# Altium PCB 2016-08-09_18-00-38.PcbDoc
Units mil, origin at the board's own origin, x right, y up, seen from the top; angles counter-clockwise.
Board outline 2000 x 4000 mil, 4 copper layers (Top Layer, MidLayer1, MidLayer2, Bottom Layer); 19 components, 14 nets, 66 pads, 68 vias.
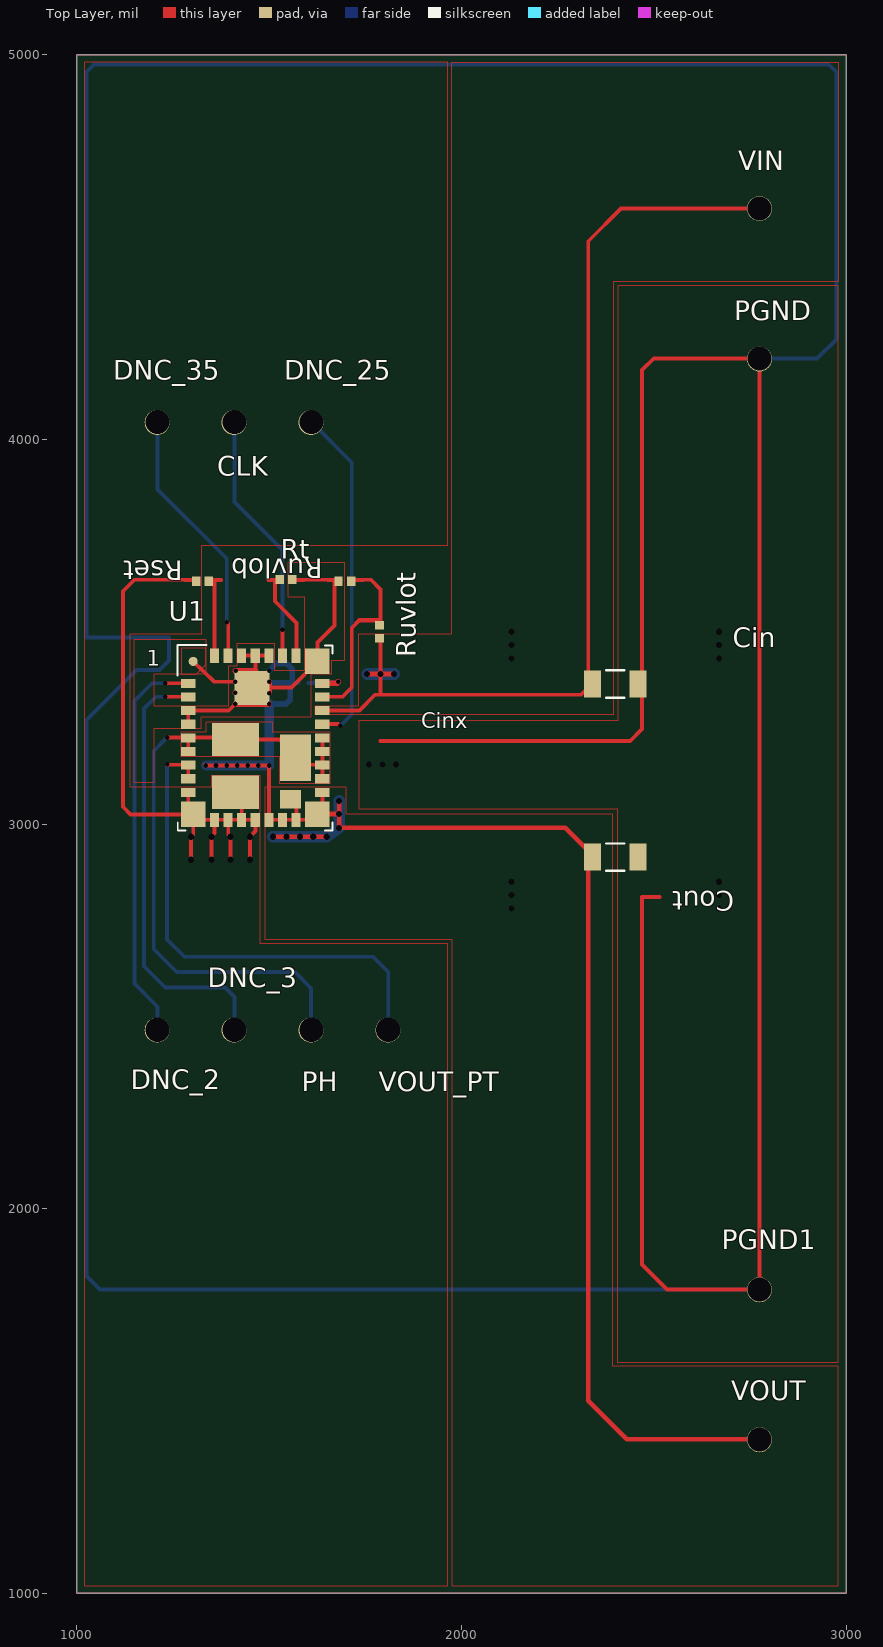
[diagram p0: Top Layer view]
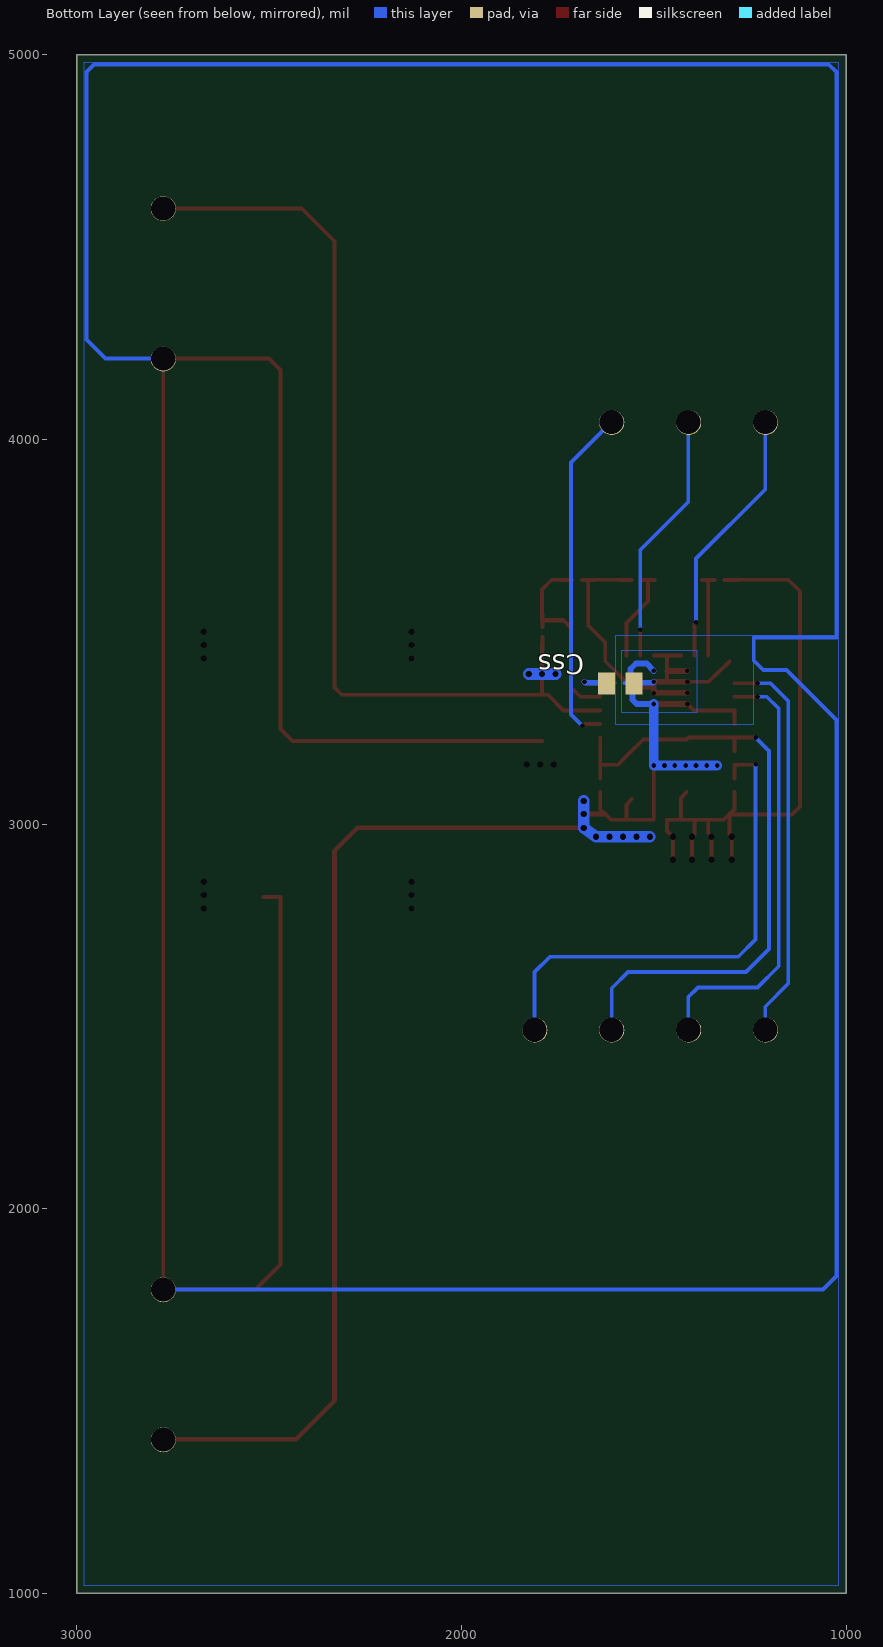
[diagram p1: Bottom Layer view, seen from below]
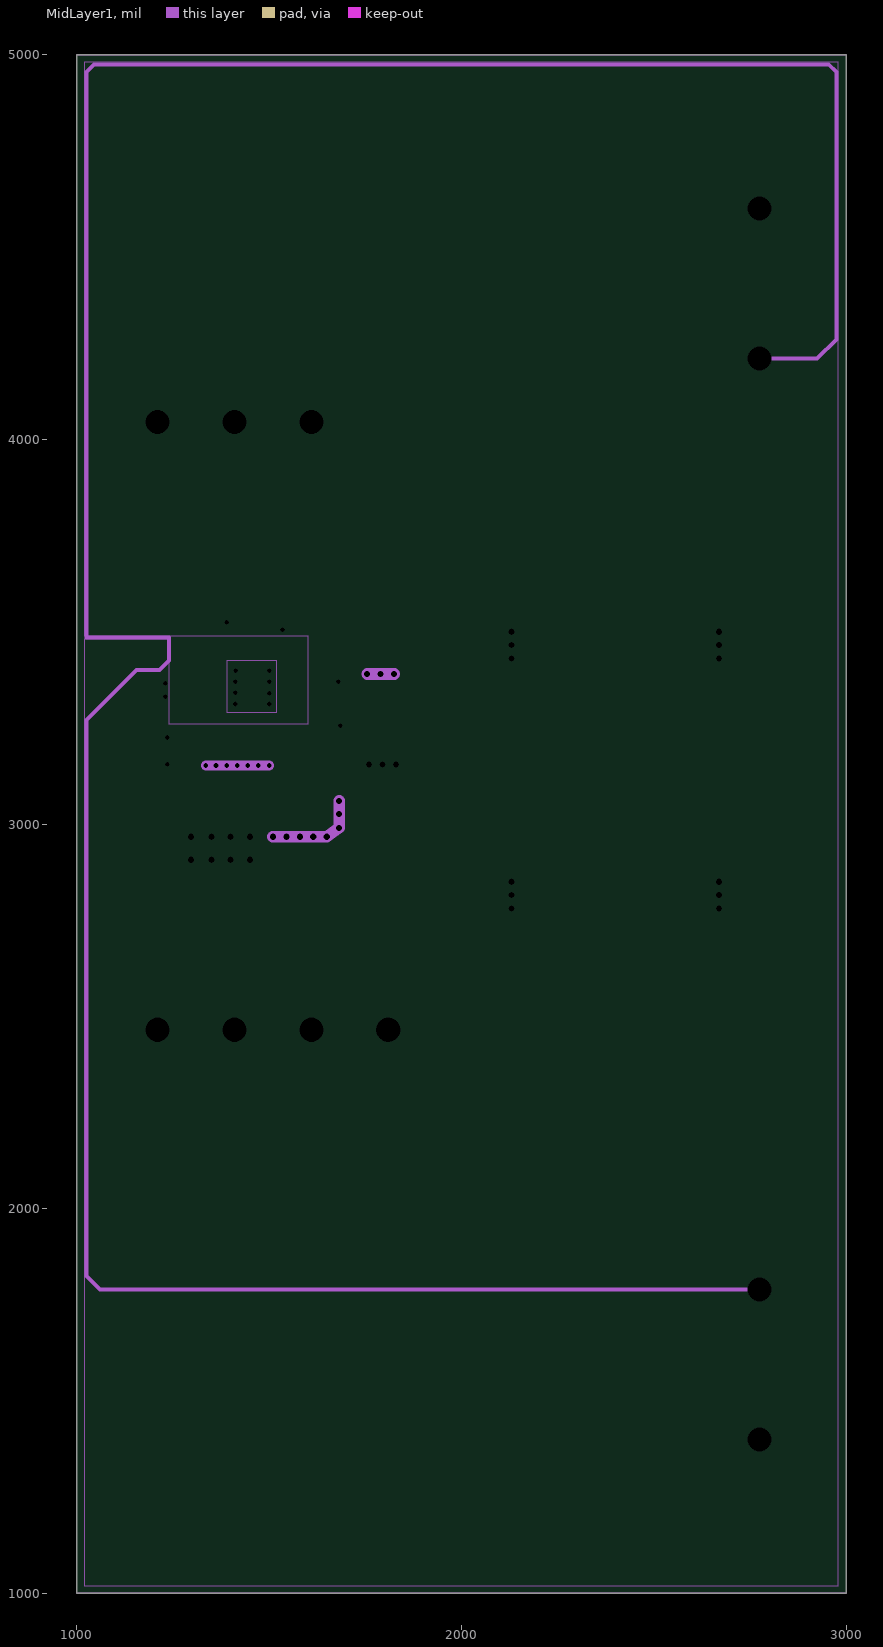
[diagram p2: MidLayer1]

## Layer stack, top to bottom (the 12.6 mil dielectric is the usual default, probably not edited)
Top Layer: signal copper 1.4
Dielectric: core 12.6, FR-4, Dk 4.8
MidLayer1: signal copper 1.4
Dielectric: prepreg 12.6, FR-4, Dk 4.8
MidLayer2: signal copper 1.4
Dielectric: core 12.6, FR-4, Dk 4.8
Bottom Layer: signal copper 1.4

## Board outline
1000,1000 3000,1000 3000,5000 1000,5000

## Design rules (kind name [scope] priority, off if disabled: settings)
PlaneConnect [All] p0: scope1count=1 scope1_0_kind=Board scope1_0_value=Board scope2count=1 scope2_0_kind=Board scope2_0_value=Board commentlength=0 planeconnectstyle=Direct reliefexpansion=20 reliefentries=4 reliefconductorwidth=10 reliefairgap=10
PlaneConnect [All] p1: planeconnectstyle=Direct reliefexpansion=20 reliefentries=4 reliefconductorwidth=10 reliefairgap=10
PolygonConnect [All] p0: scope1count=1 scope1_0_kind=Board scope1_0_value=Board scope2count=1 scope2_0_kind=Board scope2_0_value=Board commentlength=0 connectstyle=Direct reliefconductorwidth=10 reliefentries=4 polygonreliefangle="90 Angle"
PolygonConnect [All] p1: connectstyle=Direct reliefconductorwidth=10 reliefentries=4 polygonreliefangle="90 Angle"

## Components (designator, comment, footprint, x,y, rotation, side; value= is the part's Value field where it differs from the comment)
Cin "" 1206 2400,3364 r0 top
CLK "" TP-1502 1409,4044 r0 top
Cout "" 1206_190 2400,2914 r180 top
Css "" 0805 1587,3365 r180 bottom
DNC_2 "" TP-1502 1209,2464 r0 top
DNC_3 "" TP-1502 1409,2464 r0 top
DNC_25 "" TP-1502 1609,4044 r0 top
DNC_35 "" TP-1502 1209,4044 r0 top
PGND "" TP-1502 2775,4209 r0 top
PGND1 "" TP-1502 2775,1789 r0 top
PH "" TP-1502 1609,2464 r0 top
Rset "" 0402 1327,3631 r180 top
Rt "" 0402 1544,3636 r0 top
Ruvlob "" 0402 1697,3631 r180 top
Ruvlot "" 0402 1787,3500 r90 top
U1 "" RKG0041A 1464,3224 r0 top
VIN "" TP-1502 2775,4600 r0 top
VOUT "" TP-1502 2775,1399 r0 top
VOUT_PT "" TP-1502 1809,2464 r0 top

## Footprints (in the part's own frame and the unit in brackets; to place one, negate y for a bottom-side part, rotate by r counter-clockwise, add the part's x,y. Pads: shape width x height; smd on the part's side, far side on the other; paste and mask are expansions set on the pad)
0402 [mil]
  rect 22x24 smd: 1(-16.5,0) 2(16.5,0)
0805 [mil]
  rect 44x57 smd: 1(35.5,0) 2(-35.5,0)
1206 [mil]
  rect 44x71 smd: 1(-59,0) 2(59,0)
  silkscreen extent -24,-36 24,36
1206_190 [mil]
  rect 44x71 smd: 1(-59,0) 2(59,0)
  silkscreen extent -24,-36 24,36
RKG0041A [mm]
  round 0.6 smd: 1(-4.1,5.05)
  rect 0.95x0.6 smd: 2(-4.42,3.6) 3(-4.42,2.7) 4(-4.42,1.8) 5(-4.42,0.9) 6(-4.42,0) 7(-4.42,-0.9) 8(-4.42,-1.8) 9(-4.42,-2.7) 10(-4.42,-3.6) 20(4.42,-3.6) 21(4.42,-2.7) 22(4.42,-1.8) 23(4.42,-0.9) 24(4.42,0) 25(4.42,0.9) 26(4.42,1.8) 27(4.42,2.7) 28(4.42,3.6)
  rect 1.6x1.7 smd: 11(-4.1,-5.05) 19(4.1,-5.05) 29(4.1,5.05)
  rect 0.6x0.95 smd: 12(-2.7,-5.425) 13(-1.8,-5.425) 14(-0.9,-5.425) 15(0,-5.425) 16(0.9,-5.425) 17(1.8,-5.425) 18(2.7,-5.425) 30(2.7,5.425) 31(1.8,5.425) 32(0.9,5.425) 33(0,5.425) 34(-0.9,5.425) 35(-1.8,5.425) 36(-2.7,5.425)
  rect 2.3x2.25 smd: 37(-0.22,3.3)
  rect 3.1x2.2 smd: 38(-1.3,-0.11) 39(-1.3,-3.59)
  rect 1.4x1.24 smd: 40(2.33,-4.06)
  rect 2.04x3.05 smd: 41(2.65,-1.32)
  silkscreen extent -5.13,-6.11 5.12,6.12
TP-1502 [mil]
  round 65 / inner round 0 / far side round 65 hole 32: 1(0,0)

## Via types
v1: diameter 0, hole 16, Top Layer to Bottom Layer, 34 vias
v2: diameter 0, hole 12, Top Layer to Bottom Layer, 23 vias
v3: diameter 0, hole 63, Top Layer to Bottom Layer, 11 vias

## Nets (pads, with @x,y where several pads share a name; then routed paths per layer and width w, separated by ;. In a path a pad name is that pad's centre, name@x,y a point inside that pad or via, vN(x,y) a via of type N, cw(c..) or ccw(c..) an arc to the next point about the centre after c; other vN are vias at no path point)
0: Cin.2 Cout.1 PGND1.1 PGND.1 Rset.2 U1.10 U1.11 U1.12 U1.13 U1.14 U1.15 U1.39 | length 23658.6
  Top Layer w10: 1283,3634.5 Rset.2@1316,3634.5 ; U1.10@1290,3083 1290,3038 U1.11@1303,3026 ; v1(1297,2907) v1(1297,2967) 1303,2973 U1.11@1303,3026 ; Rset.2@1300,3635 1150,3635 1120,3605 1120,3045 1140,3025 1302,3025 U1.11@1303,3026 ; v1(1350,2907) v1(1350,2967) 1358,2976 U1.12@1358,3011 ; v1(1400,2907) v1(1400,2967) 1394,2973 U1.13@1394,3011 ; U1.39@1414,3083 1429,3068 U1.14@1429,3011 ; v1(1450,2907) v1(1450,2967) 1465,2982 1465,3011 U1.14@1429,3011 ; 1790,3216 2439,3216 2470,3247 2470,3460 2470,4180 2500,4210 v3(2775,4210) v3(2775,1790) 2535,1790 2470,1855 2470,2810 2515,2810 ; U1.11@1303,3026 1318,3011 U1.12@1358,3011 ; U1.12@1358,3011 U1.13@1394,3011 ; U1.13@1394,3011 U1.14@1429,3011
  MidLayer1 w10: v3(2775,1790) 1060,1790 1025,1825 1025,3270 1155,3400 1215,3400 1240,3425 1240,3485 1025,3485 1025,4955 1045,4975 2955,4975 2975,4955 2975,4260 2925,4210 v3(2775,4210)
  Bottom Layer w10: v3(2775,1790) 1060,1790 1025,1825 1025,3270 1155,3400 1215,3400 1240,3425 1240,3485 1025,3485 1025,4955 1045,4975 2955,4975 2975,4955 2975,4260 2925,4210 v3(2775,4210)
  other v1: 2670,2780 2670,2815 2670,2850 1760,3155 1795,3155 1830,3155 2670,3430 2670,3465 2670,3500
1: Cout.2 Css.1 Rt.2 Ruvlob.2 U1.1 U1.4 U1.5 U1.16 U1.17 U1.18 U1.19 U1.20 U1.29 U1.32 U1.33 U1.34 U1.37 U1.40 VOUT.1 | length 6093.6
  Top Layer w10: U1.5@1290,3260 1290,3295 1395,3295 v2(1412,3312) ; U1.1@1303,3423 1357,3370 v2(1412,3370) ; 1333,3154 v2(1335,3152) v2(1362,3152) v2(1390,3152) v2(1417,3152) v2(1445,3152) v2(1472,3152) v2(1500,3152) 1500,3151 1500,3011 1535,3011 U1.18@1571,3011 ; U1.34@1429,3438 U1.33@1465,3438 ; U1.37@1465,3370 1465,3398 U1.33@1465,3438 ; U1.37@1500,3355 1558,3355 1626,3423 1626,3472 1670,3516 1670,3635 1574,3635 ; U1.32@1500,3438 U1.33@1465,3438 ; U1.40@1557,3065 1571,3050 U1.18@1571,3011 ; Rt.2@1557,3634.5 1590,3634.5 ; U1.20@1639,3083 1639,3038 1626,3026 1611,3011 U1.18@1571,3011 ; 1653,3634.5 Ruvlob.2@1686,3634.5
  Top Layer w12: v1(1510,2967) v1(1545,2967) v1(1580,2967) v1(1615,2967) v1(1650,2967) ; U1.19@1626,3026 v1(1682,3026) ; v1(1682,3060) v1(1682,3026) ; v3(2775,1400) 2430,1400 2330,1500 2330,2810 2330,2930 2270,2990 v1(1682,2990) v1(1682,3026)
  Top Layer w15: v2(1412,3312) v2(1500,3312) ; v2(1412,3341) 1500,3341 1500,3355 v2(1500,3370) 1465,3370 v2(1412,3370) ; v2(1413,3398) U1.37@1465,3398
  MidLayer1 w25: v2(1335,3152) v2(1362,3152) v2(1390,3152) v2(1417,3152) v2(1445,3152) v2(1472,3152) v2(1500,3152)
  MidLayer1 w30: v1(1510,2967) v1(1545,2967) v1(1580,2967) v1(1615,2967) v1(1650,2967) v1(1682,2990) v1(1682,3026) v1(1682,3060)
  Bottom Layer w10: Css.1@1543,3366.5 1576,3366.5
  Bottom Layer w15: v2(1500,3312) 1544,3312 1555,3323 1555,3367 1502,3367 ; v2(1500,3370) 1502,3367 ; v2(1500,3398) 1518,3417 1546,3417 1560,3403 1560,3367 1502,3367
  Bottom Layer w25: v2(1335,3152) v2(1362,3152) v2(1390,3152) v2(1417,3152) v2(1445,3152) v2(1472,3152) v2(1500,3152) v2(1500,3312)
  Bottom Layer w30: v1(1510,2967) v1(1545,2967) v1(1580,2967) v1(1615,2967) v1(1650,2967) v1(1682,2990) v1(1682,3026) v1(1682,3060)
  other v1: 2130,2780 2130,2815 2130,2850
  other v2: 1500,3340
2: Ruvlob.1 Ruvlot.2 U1.27 | length 599
  Top Layer w10: U1.27@1639,3331 1691,3331 1715,3355 1715,3510 1734,3529 ; Ruvlob.1@1712,3634.5 1745,3634.5 ; 1729,3635 1765,3635 1790,3610 1790,3529 ; Ruvlot.2@1789.5,3512 1789.5,3545 ; 1734,3529 1735,3530 1789,3530 1790,3529 ; 1734,3529 1790,3529
3: Cin.1 Ruvlot.1 U1.26 VIN.1 | length 2733.4
  Top Layer w10: U1.26@1639,3295 1735,3295 1775,3336 1790,3336 ; 1789.5,3453 Ruvlot.1@1789.5,3486 ; 1790,3470 v1(1790,3390) 1790,3336 ; v3(2775,4600) 2415,4600 2330,4515 2330,3460 2330,3355 2311,3336 1790,3336
  Top Layer w12: v1(1755,3390) v1(1790,3390) v1(1825,3390)
  MidLayer1 w30: v1(1755,3390) v1(1790,3390) v1(1825,3390)
  Bottom Layer w30: v1(1755,3390) v1(1790,3390) v1(1825,3390)
  other v1: 2130,3430 2130,3465 2130,3500
4: Rt.1 U1.30 | length 253.2
  Top Layer w10: 1498,3634.5 Rt.1@1531,3634.5 ; 1515,3635 1515,3579 1571,3523 U1.30@1571,3438
5: Rset.1 U1.36 | length 230.4
  Top Layer w10: Rset.1@1342,3634.5 1375,3634.5 ; U1.36@1358,3438 1358,3634 1359,3635
8: PH.1 U1.6 U1.7 U1.21 U1.22 U1.23 U1.24 U1.38 U1.41 | length 1700.9
  Top Layer w10: v2(1235,3225) U1.6@1290,3225 ; U1.7@1290,3189 U1.6@1290,3225 ; U1.21@1639,3118 U1.22@1639,3154 ; U1.24@1639,3225 1639,3189 U1.22@1639,3154 ; U1.6@1290,3225 1410,3225 1414,3220 1527,3220 1569,3178 1593,3154 U1.22@1639,3154
  Bottom Layer w10: v2(1235,3225) 1200,3190 1200,2675 1260,2615 1567,2615 1609,2573 1609,2466 v3(1610,2465)
9: U1.8 U1.9 VOUT_PT.1 | length 1307.2
  Top Layer w10: v2(1235,3155) 1235,3154 1290,3154 U1.9@1290,3118
  Bottom Layer w10: v2(1235,3155) 1235,2700 1280,2655 1770,2655 1810,2615 v3(1810,2465)
10: DNC_35.1 U1.35 | length 683
  Top Layer w10: v2(1390,3525) 1394,3520 U1.35@1394,3438
  Bottom Layer w10: v3(1210,4045) 1210,3870 1390,3690 v2(1390,3525)
11: DNC_25.1 U1.25 | length 893.7
  Top Layer w10: U1.25@1639,3260 1679,3260 v2(1685,3255)
  Bottom Layer w10: v3(1610,4045) 1715,3940 1715,3285 v2(1685,3255)
12: DNC_3.1 U1.3 | length 1151
  Top Layer w10: v2(1230,3331) U1.3@1290,3331
  Bottom Layer w10: v2(1230,3331) 1206,3331 1175,3300 1175,2630 1230,2575 1385,2575 1410,2550 v3(1410,2465)
13: DNC_2.1 U1.2 | length 1038.9
  Top Layer w10: v2(1230,3366) U1.2@1290,3366
  Bottom Layer w10: v3(1210,2465) 1210,2525 1150,2585 1150,3320 1196,3366 v2(1230,3366)
14: CLK.1 U1.31 | length 658.8
  Top Layer w10: U1.31@1535,3438 1535,3504 v2(1535,3505)
  Bottom Layer w10: v3(1410,4045) 1410,3837 1535,3712 v2(1535,3505)
20: Css.2 U1.28 | length 137.9
  Top Layer w15: U1.28@1639,3366 1676,3366 v2(1680,3370)
  Bottom Layer w10: Css.2@1602,3366.5 Css.2@1635,3366.5
  Bottom Layer w15: Css.2@1619,3367 1677,3367 v2(1680,3370)

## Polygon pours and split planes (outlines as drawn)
1 on Top Layer " " (solid, pour order 0): 1272,3457 1272,3390 1310,3390 1335,3414 1335,3457
8 on Top Layer " " (solid, pour order 5): 1659,3238 1510,3238 1510,3265 1335,3265 1335,3238 1270,3238 1270,3176 1527,3176 1527,3106 1659,3106
1 on Top Layer " " (solid, pour order 6): 2980,1020 2980,1590 2394,1590 2394,3025 1700,3025 1700,3095 1489,3095 1489,2700 1975,2700 1975,1020
3 on Top Layer " " (solid, pour order 7): 2980,4980 2980,4410 2395,4410 2395,3284 1620,3284 1620,3308 1733,3308 1733,3495 1975,3495 1975,4980
1 on Top Layer " " (solid, pour order 8): 1200,3107 1150,3107 1150,3480 1335,3480 1335,3390 1200,3390 1200,3308 1395,3308 1395,3412 1417,3412 1417,3470 1514,3470 1514,3400 1593,3400 1593,3590 1550,3590 1550,3680 1695,3680 1695,3425 1661,3425 1661,3390 1608,3390 1608,3277 1322,3277 1322,3248 1200,3248
0 on Top Layer " " (solid, pour order 11): 1477,3125 1350,3125 1350,3095 1139,3095 1139,3495 1325,3495 1325,3725 1965,3725 1965,4980 1020,4980 1020,1020 1965,1020 1965,2689 1477,2689
0 on Top Layer " " (solid, pour order 12): 2980,4400 2406,4400 2406,3269 1733,3269 1733,3040 2405,3040 2405,1600 2980,1600
1 on Bottom Layer " " (solid, pour order 9): 1585,3450 1585,3290 1387,3290 1387,3450
0 on Bottom Layer " " (solid, pour order 13): 2980,4980 1020,4980 1020,3490 1600,3490 1600,3260 1240,3260 1240,3485 1020,3485 1020,1020 2980,1020
3 on MidLayer2 " " (solid, pour order 1): 2980,4980 1975,4980 1975,3495 1733,3495 1733,3284 2395,3284 2395,4410 2980,4410
1 on MidLayer2 " " (solid, pour order 2): 1275,3440 1275,3290 1655,3290 1655,3440
1 on MidLayer2 " " (solid, pour order 3): 1020,4980 1020,1020 2980,1020 2980,4400 2410,4400 2410,3270 1250,3270 1250,3505 1965,3505 1965,4980
1 on MidLayer1 " " (solid, pour order 4): 1390,3425 1390,3290 1520,3290 1520,3425
0 on MidLayer1 " " (solid, pour order 10): 2980,4980 1020,4980 1020,3490 1600,3490 1600,3260 1240,3260 1240,3480 1020,3480 1020,1020 2980,1020
no net on Top Paste "Top Layer-No Net" (solid, remove dead copper): 1510.26,3455.1 1488.61,3455.1 1488.61,3420.06 1510.26,3420.06
no net on Top Paste "Top Layer-No Net" (solid, remove dead copper): 1545.69,3455.1 1524.04,3455.1 1524.04,3420.06 1545.69,3420.06
no net on Top Paste "Top Layer-No Net" (solid, remove dead copper): 1581.13,3455.1 1559.47,3455.1 1559.47,3420.06 1581.13,3420.06
no net on Top Paste "Top Layer-No Net" (solid, remove dead copper): 1655.54,3354.91 1655.54,3376.56 1620.5,3376.56 1620.5,3354.91
no net on Top Paste "Top Layer-No Net" (solid, remove dead copper): 1655.54,3319.47 1655.54,3341.13 1620.5,3341.13 1620.5,3319.47
no net on Top Paste "Top Layer-No Net" (solid, remove dead copper): 1655.54,3284.04 1655.54,3305.69 1620.5,3305.69 1620.5,3284.04
no net on Top Paste "Top Layer-No Net" (solid, remove dead copper): 1655.54,3248.61 1655.54,3270.26 1620.5,3270.26 1620.5,3248.61
no net on Top Paste "Top Layer-No Net" (solid, remove dead copper): 1655.54,3213.17 1655.54,3234.83 1620.5,3234.83 1620.5,3213.17
no net on Top Paste "Top Layer-No Net" (solid, remove dead copper): 1655.54,3177.74 1655.54,3199.39 1620.5,3199.39 1620.5,3177.74
no net on Top Paste "Top Layer-No Net" (solid, remove dead copper): 1655.54,3142.31 1655.54,3163.96 1620.5,3163.96 1620.5,3142.31
no net on Top Paste "Top Layer-No Net" (solid, remove dead copper): 1655.54,3106.87 1655.54,3128.53 1620.5,3128.53 1620.5,3106.87
no net on Top Paste "Top Layer-No Net" (solid, remove dead copper): 1655.54,3071.44 1655.54,3093.09 1620.5,3093.09 1620.5,3071.44
no net on Top Paste "Top Layer-No Net" (solid, remove dead copper): 1549.83,3043.69 1549.83,3084.63 1530.14,3084.63 1530.14,3043.69
no net on Top Paste "Top Layer-No Net" (solid, remove dead copper): 1438.61,3348.02 1438.61,3314.55 1472.07,3314.55 1472.07,3348.02
no net on Top Paste "Top Layer-No Net" (solid, remove dead copper): 1356.52,3213.76 1356.52,3182.27 1406.91,3182.27 1406.91,3213.76
no net on Top Paste "Top Layer-No Net" (solid, remove dead copper): 1581.32,3043.69 1581.32,3084.63 1561.64,3084.63 1561.64,3043.69
no net on Top Paste "Top Layer-No Net" (solid, remove dead copper): 1649.83,3393.84 1649.83,3451.8 1601.01,3451.8 1601.01,3393.84
no net on Top Paste "Top Layer-No Net" (solid, remove dead copper): 1649.83,2996.2 1649.83,3054.16 1601.01,3054.16 1601.01,2996.2
no net on Top Paste "Top Layer-No Net" (solid, remove dead copper): 1326.99,2996.2 1326.99,3054.16 1278.17,3054.16 1278.17,2996.2
no net on Top Paste "Top Layer-No Net" (solid, remove dead copper): 1438.61,3393.29 1438.61,3359.83 1472.07,3359.83 1472.07,3393.29
no net on Top Paste "Top Layer-No Net" (solid, remove dead copper): 1356.52,3257.07 1356.52,3225.57 1406.91,3225.57 1406.91,3257.07
no net on Top Paste "Top Layer-No Net" (solid, remove dead copper): 1418.72,3257.07 1418.72,3225.57 1469.12,3225.57 1469.12,3257.07
no net on Top Paste "Top Layer-No Net" (solid, remove dead copper): 1418.72,3213.76 1418.72,3182.27 1469.12,3182.27 1469.12,3213.76
no net on Top Paste "Top Layer-No Net" (solid, remove dead copper): 1418.72,3076.76 1418.72,3045.26 1469.12,3045.26 1469.12,3076.76
no net on Top Paste "Top Layer-No Net" (solid, remove dead copper): 1418.72,3120.06 1418.72,3088.57 1469.12,3088.57 1469.12,3120.06
no net on Top Paste "Top Layer-No Net" (solid, remove dead copper): 1356.52,3120.06 1356.52,3088.57 1406.91,3088.57 1406.91,3120.06
no net on Top Paste "Top Layer-No Net" (solid, remove dead copper): 1356.52,3076.76 1356.52,3045.26 1406.91,3045.26 1406.91,3076.76
no net on Top Paste "Top Layer-No Net" (solid, remove dead copper): 1533.69,3177.94 1562.43,3177.94 1562.43,3228.33 1533.69,3228.33
no net on Top Paste "Top Layer-No Net" (solid, remove dead copper): 1574.24,3177.94 1602.98,3177.94 1602.98,3228.33 1574.24,3228.33
no net on Top Paste "Top Layer-No Net" (solid, remove dead copper): 1533.69,3115.73 1562.43,3115.73 1562.43,3166.13 1533.69,3166.13
no net on Top Paste "Top Layer-No Net" (solid, remove dead copper): 1574.24,3115.73 1602.98,3115.73 1602.98,3166.13 1574.24,3166.13
no net on Top Paste "Top Layer-No Net" (solid, remove dead copper): 1346.87,2992.9 1368.53,2992.9 1368.53,3027.94 1346.87,3027.94
no net on Top Paste "Top Layer-No Net" (solid, remove dead copper): 1382.31,2992.9 1403.96,2992.9 1403.96,3027.94 1382.31,3027.94
no net on Top Paste "Top Layer-No Net" (solid, remove dead copper): 1417.74,2992.9 1439.39,2992.9 1439.39,3027.94 1417.74,3027.94
no net on Top Paste "Top Layer-No Net" (solid, remove dead copper): 1453.17,2992.9 1474.83,2992.9 1474.83,3027.94 1453.17,3027.94
no net on Top Paste "Top Layer-No Net" (solid, remove dead copper): 1488.61,2992.9 1510.26,2992.9 1510.26,3027.94 1488.61,3027.94
no net on Top Paste "Top Layer-No Net" (solid, remove dead copper): 1524.04,2992.9 1545.69,2992.9 1545.69,3027.94 1524.04,3027.94
no net on Top Paste "Top Layer-No Net" (solid, remove dead copper): 1559.47,2992.9 1581.13,2992.9 1581.13,3027.94 1559.47,3027.94
no net on Top Solder "Top Layer-No Net" (solid, remove dead copper): 1410.06,3309.63 1433.68,3309.63 1433.68,3398.21 1410.06,3398.21
no net on Top Solder "Top Layer-No Net" (solid, remove dead copper): 1476.99,3309.63 1500.61,3309.63 1500.61,3398.21 1476.99,3398.21
no net on Top Paste "Top Layer-No Net" (solid, remove dead copper): 1278.17,3451.8 1278.17,3393.84 1306.98,3393.84 1326.99,3413.76 1326.99,3451.8 1278.17,3451.8

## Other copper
Multi-Layer:
  the board outline again, w1

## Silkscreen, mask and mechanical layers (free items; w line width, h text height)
Top Overlay:
  text "1" at 1182,3412 h40
  text "Cinx" at 1896,3249 h40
